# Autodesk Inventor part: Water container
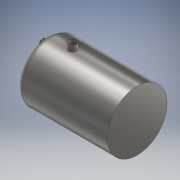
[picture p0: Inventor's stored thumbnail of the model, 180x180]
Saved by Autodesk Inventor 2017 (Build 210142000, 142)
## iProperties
Created: 2020-03
Part Number: Water container
Material: Stainless Steel, 440C
Document SubType Name: Modeling
Designer: user
Density: 7.75 g/cm^3
Appearance: Semi-Polished
Author: user
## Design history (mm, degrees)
sketch "Sketch1"
  geometry: L1 (0, 0)-(285, 0); L2 (300, -15)-(300, -100); L3 (0, -100)-(0, 0); L4 (298, -100)-(298, -15); L5 (285, -2)-(2, -2); L6 (2, -2)-(2, -100); L7 (300, -100)-(298, -100); L8 (2, -100)-(0, -100); A1 r 15 centre (285, -15) between (300, -15) and (285, 0); A2 r 13 centre (285, -15) between (298, -15) and (285, -2); 1 further point
  constraints: 16 end point, 4 perpendicular, 4 point on circle, 3 horizontal, 2 centre point, 2 point on line, 2 tangent, 1 other
  dimensions: "d0" = 300 distance of L1.start point (300, 0); "d1" = 100 distance of point (300, 0) L2.end; "d2" = 15 radius of A1; "d3" = 2 distance between parallel lines of L2 L4
revolve "Revolution1" sketch "Sketch1" stored, may be unused: angle "d4" = 90 deg
sketch "Sketch2"
  geometry: 2 further points
  dimensions: "d5" = 170 distance of point (100, 0) point (-70, 0)
hole "Hole1" sketch "Sketch2" at (-70, 0) diameter "d6" = 6; stored, may be unused: countersink angle "d10" = 90 deg, drill point angle "d12" = 118 deg; dims "d7" = 6, "d8" = 4, "d9" = 2, "d11" = 8
thread "Thread1" dims "d13" = 10, "d14" = 0
chamfer "Chamfer1" distance "d15" = 0.2; stored, may be unused: second distance "d16" = 2, angle "d17" = 45 deg
sketch "Sketch3"
  geometry: C1 r 12.7 at (67.747, 0); 1 further point
  constraints: 1 centre point
  dimensions: "d18" = 25.4 diameter of C1
extrude "Extrusion1" join sketch "Sketch3" distance "d19" = 15; taper "d20" = 0 deg
sketch "Sketch5"
  geometry: L1 (315, -44.953)-(315, -19.553) reference; L2 (315, -19.553)-(312, -19.553); L3 (300, -19.553)-(315, -19.553) reference; L4 (312, -19.553)-(313.5, -18.553); L5 (313.5, -18.553)-(315, -19.553); 1 further point
  constraints: 6 end point, 1 point on line
  dimensions: "d22" = 3 distance of L1.end L2.end; "d31" = 1.5 horizontal distance of L2.end L4.end; "d32" = 1 distance from line of L2 L4.end
sketch "Sketch4"
  geometry: L1 (315, -44.953)-(315, -19.553) reference; L2 (315, -32.253)-(308, -32.253); 1 further point
  constraints: 2 end point, 1 horizontal, 1 midpoint
  dimensions: "d21" = 7 distance of L2.start L2.end
coil "Coil1" sketch "Sketch5", "Sketch4" pitch "d23" = 6; turns "d25" = 1.5; dims "d24" = 10, "d26" = 0, angle "d27" = 90 deg, angle "d28" = 90 deg, "d29" = 0, "d30" = 0
sketch "Sketch6"
  geometry: C1 r 11.5 at (0, 0); 1 further point
  constraints: 1 centre point
  dimensions: "d33" = 23 diameter of C1
extrude "Extrusion2" cut sketch "Sketch6" distance "d34" = 20; taper "d35" = 0 deg
sketch "Sketch7"
  geometry: C1 r 12.7 at (-215.33, 0); 1 further point
  constraints: 1 centre point
  dimensions: "d36" = 25.4 diameter of C1
extrude "Extrusion3" join sketch "Sketch7" stored distance "d37" = 20; taper "d38" = 0 deg
sketch "Sketch8"
  geometry: C1 r 12.7 at (-215.33, 0); A1 r 12.7 centre (-215.33, 0) between (-202.63, 0) and (-228.03, 0) reference; 1 further point
  constraints: 1 centre point, 1 coincident
extrude "Extrusion4" join sketch "Sketch8" distance "d39" = 20; taper "d40" = 0 deg
sketch "Sketch9"
  geometry: C1 r 12.7 at (0, 0) reference; C2 r 11.5 at (0, 0); 1 further point
  constraints: 1 centre point, 1 coincident
  dimensions: "d41" = 23 diameter of C2
extrude "Extrusion5" cut sketch "Sketch9" distance "d42" = 30; taper "d43" = 0 deg
sketch "Sketch10"
  geometry: L1 (228.03, 20)-(228.03, 0) reference; L2 (228.03, 16)-(228.03, 18); L3 (228.03, 20)-(202.63, 20) reference; L4 (203.83, 20)-(226.83, 20) reference; L5 (215.33, 20)-(215.33, 26.797); A1 r 1 centre (228.03, 17) between (228.03, 16) and (228.03, 18); 1 further point
  constraints: 4 end point, 3 point on line, 2 point on circle, 1 centre point, 1 collinear, 1 midpoint, 1 vertical
  dimensions: "d44" = 2 diameter of A1; "d45" = 3 distance from line of L3 A1.centre
revolve "Revolution2" sketch "Sketch10" stored, may be unused: angle "d46" = 90 deg
body "Solid1"
